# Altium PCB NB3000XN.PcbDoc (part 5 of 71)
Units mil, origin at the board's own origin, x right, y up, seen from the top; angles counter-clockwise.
Board outline 9527.56 x 6929.77 mil, 6 copper layers (Top Layer, GND+SHIELD, MidLayer1, MidLayer2, P2 - 3V3+5V0, Bottom Layer), stack 62.375 mil thick; 832 components, 1027 nets, 4655 pads, 4981 vias.
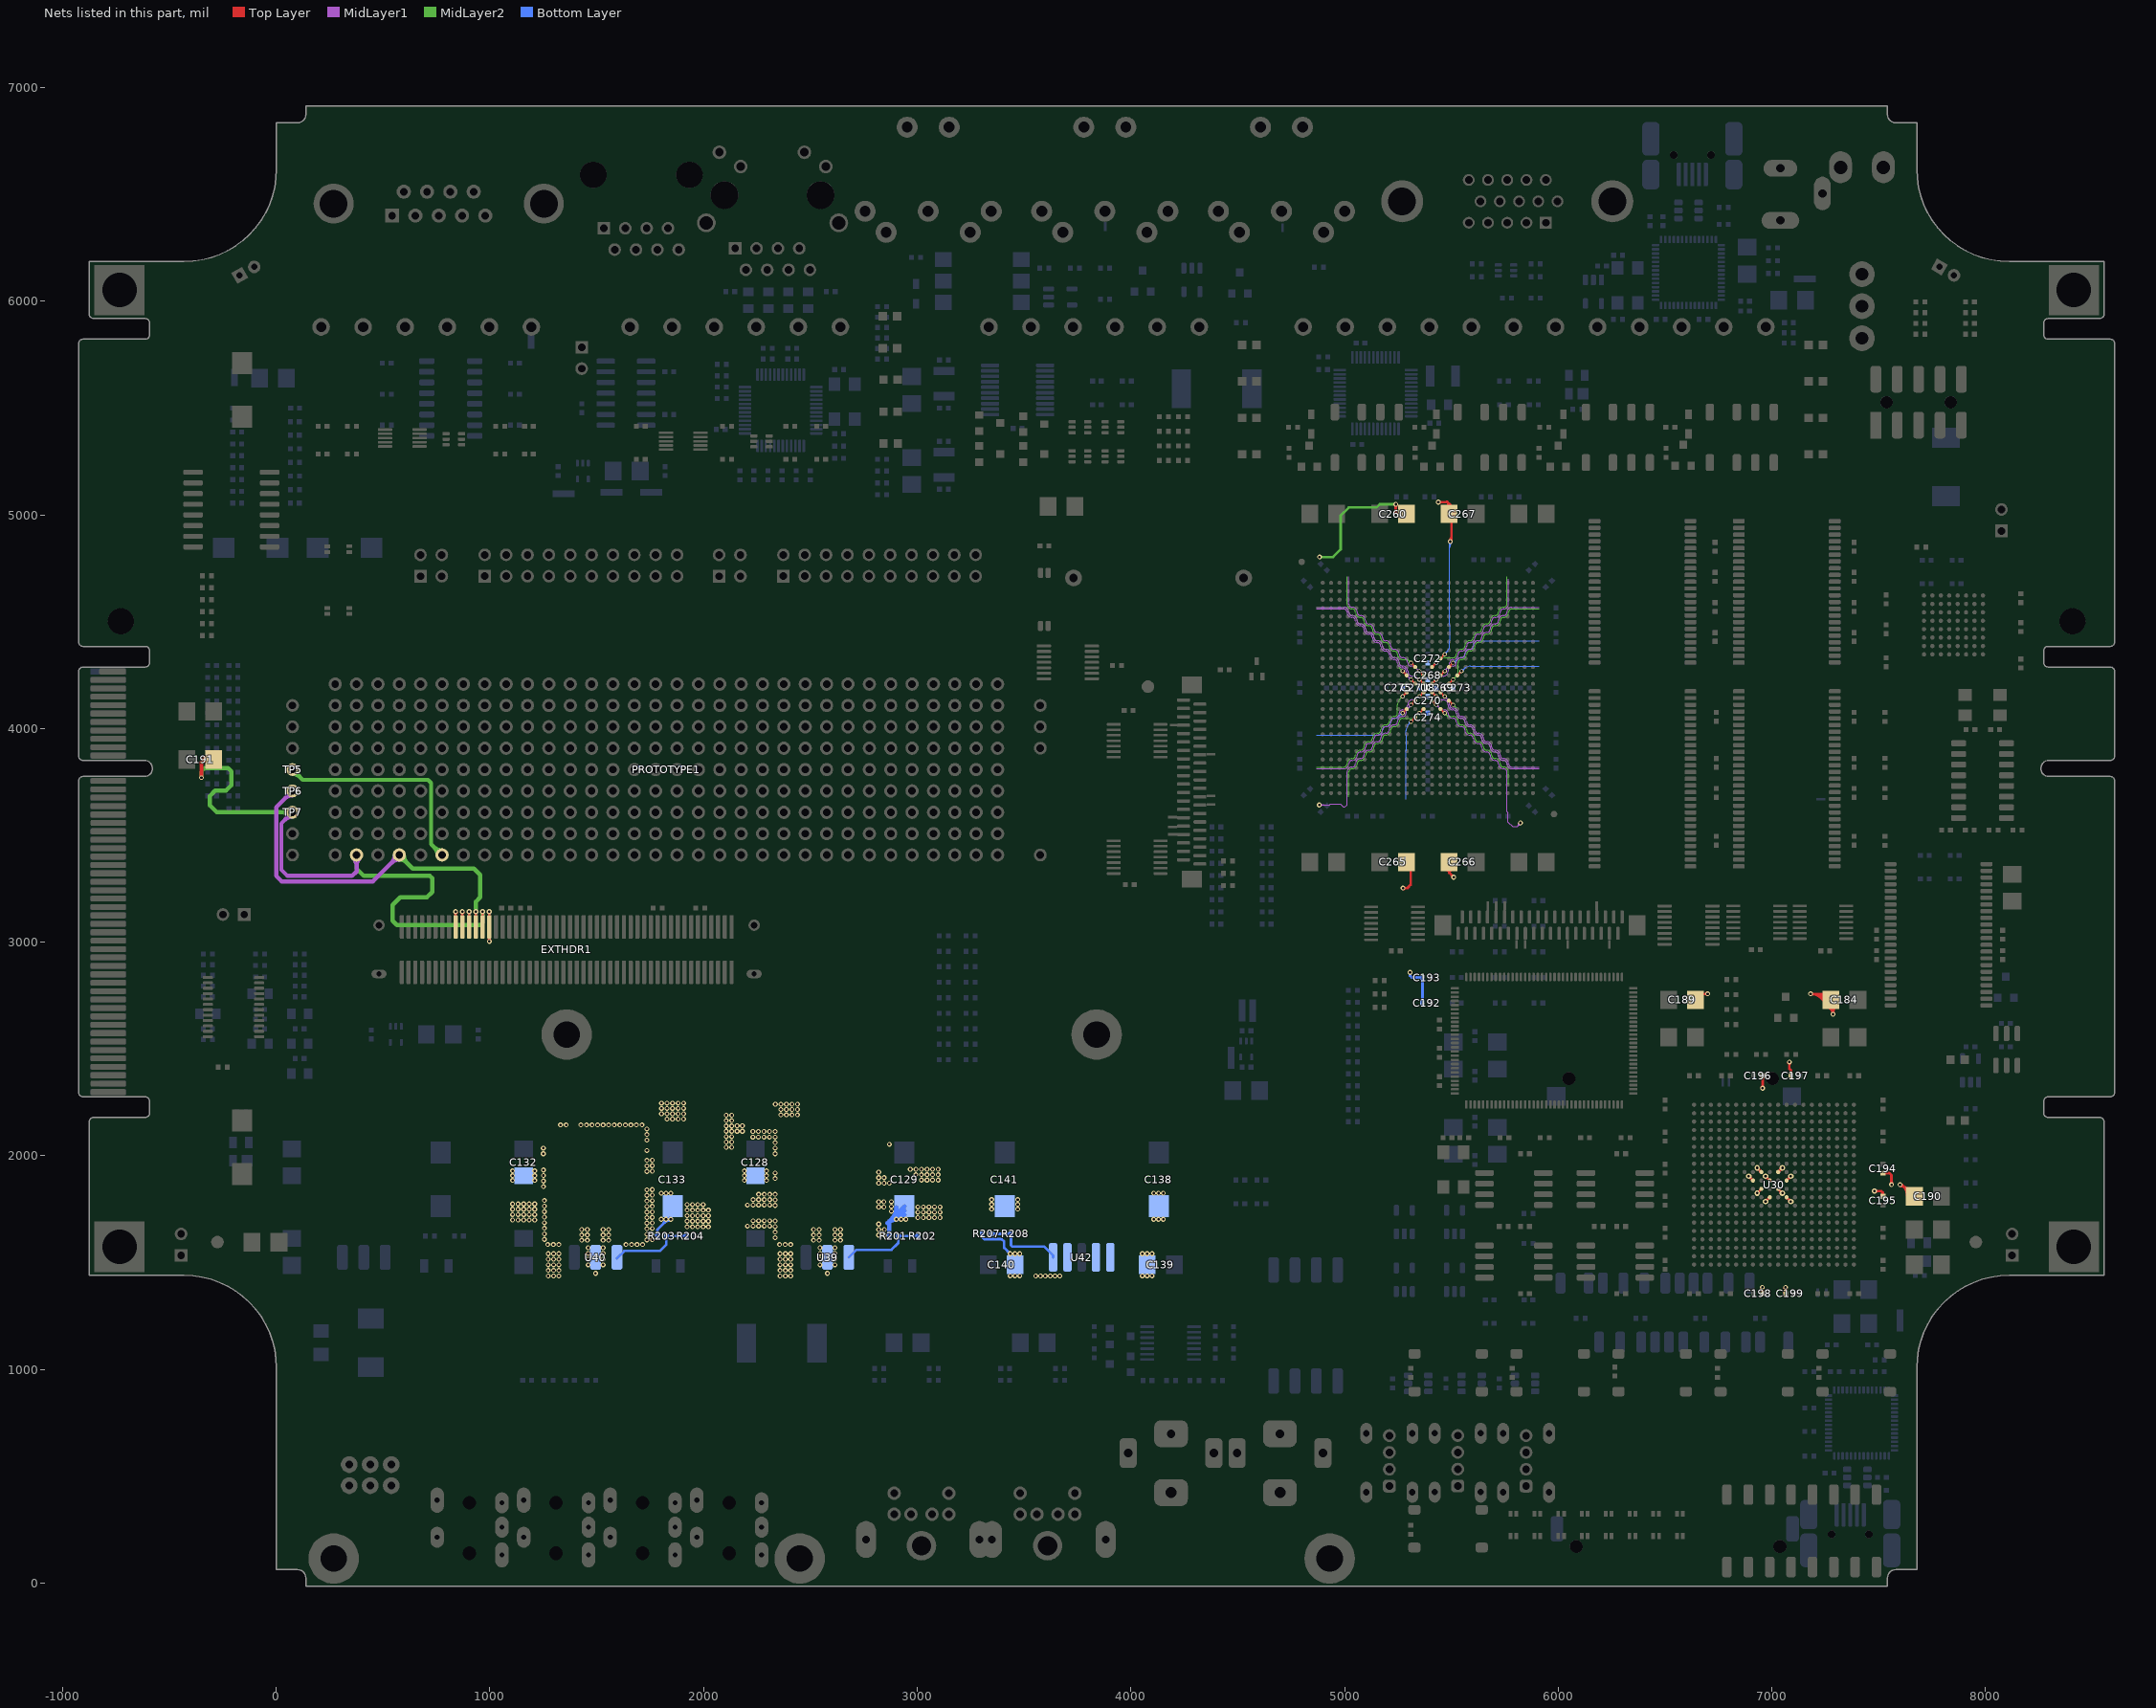
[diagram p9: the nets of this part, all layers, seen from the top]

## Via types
v1: diameter 23, hole 11.81, Top Layer to Bottom Layer, 3672 vias
v2: diameter 26, hole 11.81, Top Layer to Bottom Layer, 461 vias
v3: diameter 19, hole 11.81, Top Layer to Bottom Layer, tented both sides, 396 vias
v4: diameter 23.62, hole 11.81, Top Layer to Bottom Layer, 288 vias
v5: diameter 20, hole 11.81, Top Layer to Bottom Layer, 91 vias
v6: diameter 23, hole 11.81, Top Layer to Bottom Layer, tented both sides, 50 vias
v7: diameter 31, hole 11.81, Top Layer to Bottom Layer, 15 vias
v8: diameter 27.56, hole 11.81, Top Layer to Bottom Layer, tented both sides, 4 vias
v9: diameter 29, hole 11.81, Top Layer to Bottom Layer, 3 vias
v10: diameter 21, hole 11.81, Top Layer to Bottom Layer, 1 vias

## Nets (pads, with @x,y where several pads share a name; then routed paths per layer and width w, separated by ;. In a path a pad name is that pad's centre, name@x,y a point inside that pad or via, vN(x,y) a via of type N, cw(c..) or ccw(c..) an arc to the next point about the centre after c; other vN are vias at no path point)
1V2: C140.1 C141.1 C184.1 C189.1 C190.1 C191.1 C192.1 C193.1 C194.1 C195.1 C196.1 C197.1 C198.1 C199.1 C260.1 C265.1 C266.1 C267.1 C268.1 C269.1 C270.1 C271.1 C272.1 C273.1 C274.1 C275.1 EXTHDR1.73 EXTHDR1.75 PROTOTYPE1.2 R207.2 TP7.1 U8.K15 U8.L12 U8.L14 U8.L16 U8.M11 U8.M13 U8.M15 U8.M17 U8.N12 U8.N13 U8.N14 U8.N16 U8.P11 U8.P13 U8.P14 U8.P15 U8.R12 U8.R14 U8.R16 U8.T11 U8.T13 U8.T15 U8.U12 U30.J10 U30.J12 U30.K9 U30.K11 U30.L10 U30.L12 U30.M9 U30.M11 U30.N10 U42.4 | length 25616.4
  Top Layer w4: v3(5271.89,4071.89) U8.T11@5291.57,4091.57 ; v3(5271.89,4150.63) U8.P11@5291.57,4170.31 ; v3(5271.89,4268.74) U8.M11@5291.57,4249.06 ; U8.T11@5284.07,4091.57 cw(c5265.97,4091.57) 5278.77,4078.77 cw(c5291.57,4065.97) U8.T11@5291.57,4084.07 ; U8.P11@5284.07,4170.32 cw(c5265.97,4170.32) 5278.77,4157.51 cw(c5291.57,4144.71) U8.P11@5291.57,4162.81 ; U8.M11@5284.07,4249.06 ccw(c5265.97,4249.06) 5278.77,4261.86 ccw(c5291.57,4274.66) U8.M11@5291.57,4256.56 ; U8.T11@5284.23,4091.57 cw(c5266.51,4091.57) 5279.04,4079.04 cw(c5291.57,4066.51) U8.T11@5291.57,4084.23 ; U8.P11@5284.23,4170.32 cw(c5266.51,4170.32) 5279.04,4157.78 cw(c5291.57,4145.25) U8.P11@5291.57,4162.97 ; U8.M11@5284.23,4249.06 ccw(c5266.51,4249.06) 5279.04,4261.59 ccw(c5291.57,4274.12) U8.M11@5291.57,4256.4 ; v3(5311.26,4032.52) U8.U12@5330.94,4052.2 ; v3(5311.26,4111.26) U8.R12@5330.94,4130.94 ; v3(5311.26,4229.37) U8.N12@5330.94,4209.69 ; v3(5311.26,4308.11) U8.L12@5330.94,4288.43 ; U8.U12@5323.44,4052.2 cw(c5305.34,4052.2) 5318.14,4039.4 cw(c5330.94,4026.6) U8.U12@5330.94,4044.7 ; U8.R12@5323.44,4130.94 cw(c5305.34,4130.94) 5318.14,4118.14 cw(c5330.94,4105.34) U8.R12@5330.94,4123.44 ; U8.N12@5323.44,4209.69 ccw(c5305.34,4209.68) 5318.14,4222.49 ccw(c5330.94,4235.29) U8.N12@5330.94,4217.19 ; U8.L12@5323.44,4288.43 ccw(c5305.34,4288.43) 5318.14,4301.23 ccw(c5330.94,4314.03) U8.L12@5330.94,4295.93 ; U8.U12@5323.6,4052.2 cw(c5305.88,4052.2) 5318.41,4039.67 cw(c5330.94,4027.14) U8.U12@5330.94,4044.86 ; U8.R12@5323.6,4130.94 cw(c5305.88,4130.94) 5318.41,4118.41 cw(c5330.94,4105.88) U8.R12@5330.94,4123.6 ; U8.N12@5323.6,4209.69 ccw(c5305.88,4209.68) 5318.41,4222.22 ccw(c5330.94,4234.75) U8.N12@5330.94,4217.03 ; U8.L12@5323.6,4288.43 ccw(c5305.88,4288.43) 5318.41,4300.96 ccw(c5330.94,4313.49) U8.L12@5330.94,4295.77 ; v3(5350.63,4071.89) U8.T13@5370.31,4091.57 ; v3(5350.63,4150.63) U8.P13@5370.31,4170.31 ; v3(5350.63,4229.37) U8.N13@5370.31,4209.69 ; v3(5350.63,4268.74) U8.M13@5370.31,4249.06 ; U8.T13@5362.81,4091.57 cw(c5344.71,4091.57) 5357.51,4078.77 cw(c5370.31,4065.97) U8.T13@5370.31,4084.07 ; U8.P13@5362.81,4170.32 cw(c5344.71,4170.32) 5357.51,4157.51 cw(c5370.31,4144.71) U8.P13@5370.31,4162.81 ; U8.N13@5362.81,4209.69 ccw(c5344.71,4209.68) 5357.51,4222.49 ccw(c5370.31,4235.29) U8.N13@5370.31,4217.19 ; U8.M13@5362.81,4249.06 ccw(c5344.71,4249.06) 5357.51,4261.86 ccw(c5370.31,4274.66) U8.M13@5370.31,4256.56 ; U8.T13@5362.97,4091.57 cw(c5345.25,4091.57) 5357.78,4079.04 cw(c5370.31,4066.51) U8.T13@5370.31,4084.23 ; U8.P13@5362.97,4170.32 cw(c5345.25,4170.32) 5357.78,4157.78 cw(c5370.31,4145.25) U8.P13@5370.31,4162.97 ; U8.N13@5362.97,4209.69 ccw(c5345.25,4209.68) 5357.78,4222.22 ccw(c5370.31,4234.75) U8.N13@5370.31,4217.03 ; U8.M13@5362.97,4249.06 ccw(c5345.25,4249.06) 5357.78,4261.59 ccw(c5370.31,4274.12) U8.M13@5370.31,4256.4 ; U8.R14@5409.69,4123.44 cw(c5409.69,4105.34) 5422.49,4118.14 cw(c5435.29,4130.94) U8.R14@5417.19,4130.94 ; U8.R14@5409.69,4123.6 cw(c5409.69,4105.88) 5422.22,4118.41 cw(c5434.75,4130.94) U8.R14@5417.03,4130.94 ; U8.R14@5409.69,4130.94 v3(5429.37,4111.26) ; U8.P14@5409.69,4162.81 cw(c5409.69,4144.71) 5422.49,4157.51 cw(c5435.29,4170.32) U8.P14@5417.19,4170.32 ; U8.P14@5409.69,4162.97 cw(c5409.69,4145.25) 5422.22,4157.78 cw(c5434.75,4170.32) U8.P14@5417.03,4170.32 ; U8.P14@5409.69,4170.31 v3(5429.37,4150.63) ; U8.N14@5409.69,4209.69 v3(5429.37,4229.37) ; U8.N14@5409.69,4217.03 ccw(c5409.69,4234.75) 5422.22,4222.22 ccw(c5434.75,4209.68) U8.N14@5417.03,4209.69 ; U8.N14@5409.69,4217.19 ccw(c5409.69,4235.29) 5422.49,4222.49 ccw(c5435.29,4209.68) U8.N14@5417.19,4209.69 ; U8.L14@5409.69,4288.43 v3(5429.37,4308.11) ; U8.L14@5409.69,4295.77 ccw(c5409.69,4313.49) 5422.22,4300.96 ccw(c5434.75,4288.43) U8.L14@5417.03,4288.43 ; U8.L14@5409.69,4295.93 ccw(c5409.69,4314.03) 5422.49,4301.23 ccw(c5435.29,4288.43) U8.L14@5417.19,4288.43 ; U8.T15@5449.06,4084.07 cw(c5449.06,4065.97) 5461.86,4078.77 cw(c5474.66,4091.57) U8.T15@5456.56,4091.57 ; U8.T15@5449.06,4084.23 cw(c5449.06,4066.51) 5461.59,4079.04 cw(c5474.12,4091.57) U8.T15@5456.4,4091.57 ; U8.T15@5449.06,4091.57 v3(5468.74,4071.89) ; U8.P15@5449.06,4162.81 cw(c5449.06,4144.71) 5461.86,4157.51 cw(c5474.66,4170.32) U8.P15@5456.56,4170.32 ; U8.P15@5449.06,4162.97 cw(c5449.06,4145.25) 5461.59,4157.78 cw(c5474.12,4170.32) U8.P15@5456.4,4170.32 ; U8.P15@5449.06,4170.31 v3(5468.74,4150.63) ; U8.M15@5449.06,4249.06 v3(5468.74,4268.74) ; U8.M15@5449.06,4256.4 ccw(c5449.06,4274.12) 5461.59,4261.59 ccw(c5474.12,4249.06) U8.M15@5456.4,4249.06 ; U8.M15@5449.06,4256.56 ccw(c5449.06,4274.66) 5461.86,4261.86 ccw(c5474.66,4249.06) U8.M15@5456.56,4249.06 ; U8.K15@5449.06,4327.8 v3(5468.74,4347.48) ; U8.K15@5449.06,4335.14 ccw(c5449.06,4352.86) 5461.59,4340.33 ccw(c5474.12,4327.8) U8.K15@5456.4,4327.8 ; U8.K15@5449.06,4335.3 ccw(c5449.06,4353.4) 5461.86,4340.6 ccw(c5474.66,4327.8) U8.K15@5456.56,4327.8 ; U8.R16@5488.43,4123.44 cw(c5488.43,4105.34) 5501.23,4118.14 cw(c5514.03,4130.94) U8.R16@5495.93,4130.94 ; U8.R16@5488.43,4123.6 cw(c5488.43,4105.88) 5500.96,4118.41 cw(c5513.49,4130.94) U8.R16@5495.77,4130.94 ; U8.R16@5488.43,4130.94 v3(5508.11,4111.26) ; U8.N16@5488.43,4209.69 v3(5508.11,4229.37) ; U8.N16@5488.43,4217.03 ccw(c5488.43,4234.75) 5500.96,4222.22 ccw(c5513.49,4209.68) U8.N16@5495.77,4209.69 ; U8.N16@5488.43,4217.19 ccw(c5488.43,4235.29) 5501.23,4222.49 ccw(c5514.03,4209.68) U8.N16@5495.93,4209.69 ; U8.L16@5488.43,4288.43 v3(5508.11,4308.11) ; U8.L16@5488.43,4295.77 ccw(c5488.43,4313.49) 5500.96,4300.96 ccw(c5513.49,4288.43) U8.L16@5495.77,4288.43 ; U8.L16@5488.43,4295.93 ccw(c5488.43,4314.03) 5501.23,4301.23 ccw(c5514.03,4288.43) U8.L16@5495.93,4288.43 ; U8.M17@5527.8,4249.06 v3(5547.48,4268.74) ; U8.M17@5527.8,4256.4 ccw(c5527.8,4274.12) 5540.33,4261.59 ccw(c5552.86,4249.06) U8.M17@5535.14,4249.06 ; U8.M17@5527.8,4256.56 ccw(c5527.8,4274.66) 5540.6,4261.86 ccw(c5553.4,4249.06) U8.M17@5535.3,4249.06 ; C196.1@6956.86,2375 C196.1@6956.86,2376.19 ; v1@5234.86,5050.04 5240,5050.04 v1@5234.9,5050 ; v1@5234.86,5050.04 v1@5234.9,5050 ; 5284.69,4084.69 cw(c5271.89,4097.5) 5271.89,4079.39 ccw(c5271.89,4097.5) 5284.69,4084.69 ; 5284.69,4084.69 ccw(c5297.5,4071.89) 5279.39,4071.89 cw(c5297.5,4071.89) 5284.69,4084.69 ; 5284.69,4163.43 cw(c5271.89,4176.24) 5271.89,4158.13 ccw(c5271.89,4176.24) 5284.69,4163.43 ; 5284.69,4163.43 ccw(c5297.5,4150.63) 5279.39,4150.63 cw(c5297.5,4150.63) 5284.69,4163.43 ; 5284.69,4255.94 cw(c5297.5,4268.74) 5279.39,4268.74 ccw(c5297.5,4268.74) 5284.69,4255.94 ; 5284.69,4255.94 ccw(c5271.89,4243.13) 5271.89,4261.24 cw(c5271.89,4243.13) 5284.69,4255.94 ; 5324.06,4045.32 cw(c5311.26,4058.13) 5311.26,4040.02 ccw(c5311.26,4058.13) 5324.06,4045.32 ; 5324.06,4045.32 ccw(c5336.87,4032.52) 5318.76,4032.52 cw(c5336.87,4032.52) 5324.06,4045.32 ; 5324.06,4124.06 cw(c5311.26,4136.87) 5311.26,4118.76 ccw(c5311.26,4136.87) 5324.06,4124.06 ; 5324.06,4124.06 ccw(c5336.87,4111.26) 5318.76,4111.26 cw(c5336.87,4111.26) 5324.06,4124.06 ; 5324.06,4216.57 cw(c5336.87,4229.37) 5318.76,4229.37 ccw(c5336.87,4229.37) 5324.06,4216.57 ; 5324.06,4216.57 ccw(c5311.26,4203.76) 5311.26,4221.87 cw(c5311.26,4203.76) 5324.06,4216.57 ; 5324.06,4295.31 cw(c5336.87,4308.11) 5318.76,4308.11 ccw(c5336.87,4308.11) 5324.06,4295.31 ; 5324.06,4295.31 ccw(c5311.26,4282.5) 5311.26,4300.61 cw(c5311.26,4282.5) 5324.06,4295.31 ; 5363.43,4084.69 cw(c5350.63,4097.5) 5350.63,4079.39 ccw(c5350.63,4097.5) 5363.43,4084.69 ; 5363.43,4084.69 ccw(c5376.24,4071.89) 5358.13,4071.89 cw(c5376.24,4071.89) 5363.43,4084.69 ; 5363.43,4163.43 cw(c5350.63,4176.24) 5350.63,4158.13 ccw(c5350.63,4176.24) 5363.43,4163.43 ; 5363.43,4163.43 ccw(c5376.24,4150.63) 5358.13,4150.63 cw(c5376.24,4150.63) 5363.43,4163.43 ; 5363.43,4216.57 cw(c5376.24,4229.37) 5358.13,4229.37 ccw(c5376.24,4229.37) 5363.43,4216.57 ; 5363.43,4216.57 ccw(c5350.63,4203.76) 5350.63,4221.87 cw(c5350.63,4203.76) 5363.43,4216.57 ; 5363.43,4255.94 cw(c5376.24,4268.74) 5358.13,4268.74 ccw(c5376.24,4268.74) 5363.43,4255.94 ; 5363.43,4255.94 ccw(c5350.63,4243.13) 5350.63,4261.24 cw(c5350.63,4243.13) 5363.43,4255.94 ; 5416.57,4124.06 cw(c5403.76,4111.26) 5421.87,4111.26 ccw(c5403.76,4111.26) 5416.57,4124.06 ; 5416.57,4124.06 ccw(c5429.37,4136.87) 5429.37,4118.76 cw(c5429.37,4136.87) 5416.57,4124.06 ; 5416.57,4163.43 cw(c5403.76,4150.63) 5421.87,4150.63 ccw(c5403.76,4150.63) 5416.57,4163.43 ; 5416.57,4163.43 ccw(c5429.37,4176.24) 5429.37,4158.13 cw(c5429.37,4176.24) 5416.57,4163.43 ; 5416.57,4216.57 cw(c5429.37,4203.76) 5429.37,4221.87 ccw(c5429.37,4203.76) 5416.57,4216.57 ; 5416.57,4216.57 ccw(c5403.76,4229.37) 5421.87,4229.37 cw(c5403.76,4229.37) 5416.57,4216.57 ; 5416.57,4295.31 cw(c5429.37,4282.5) 5429.37,4300.61 ccw(c5429.37,4282.5) 5416.57,4295.31 ; 5416.57,4295.31 ccw(c5403.76,4308.11) 5421.87,4308.11 cw(c5403.76,4308.11) 5416.57,4295.31 ; 5455.94,4084.69 cw(c5443.13,4071.89) 5461.24,4071.89 ccw(c5443.13,4071.89) 5455.94,4084.69 ; 5455.94,4084.69 ccw(c5468.74,4097.5) 5468.74,4079.39 cw(c5468.74,4097.5) 5455.94,4084.69 ; 5455.94,4163.43 cw(c5443.13,4150.63) 5461.24,4150.63 ccw(c5443.13,4150.63) 5455.94,4163.43 ; 5455.94,4163.43 ccw(c5468.74,4176.24) 5468.74,4158.13 cw(c5468.74,4176.24) 5455.94,4163.43 ; 5455.94,4255.94 cw(c5468.74,4243.13) 5468.74,4261.24 ccw(c5468.74,4243.13) 5455.94,4255.94 ; 5455.94,4255.94 ccw(c5443.13,4268.74) 5461.24,4268.74 cw(c5443.13,4268.74) 5455.94,4255.94 ; 5455.94,4334.68 cw(c5468.74,4321.87) 5468.74,4339.98 ccw(c5468.74,4321.87) 5455.94,4334.68 ; 5455.94,4334.68 ccw(c5443.13,4347.48) 5461.24,4347.48 cw(c5443.13,4347.48) 5455.94,4334.68 ; 5495.31,4124.06 cw(c5482.5,4111.26) 5500.61,4111.26 ccw(c5482.5,4111.26) 5495.31,4124.06 ; 5495.31,4124.06 ccw(c5508.11,4136.87) 5508.11,4118.76 cw(c5508.11,4136.87) 5495.31,4124.06 ; 5495.31,4216.57 cw(c5508.11,4203.76) 5508.11,4221.87 ccw(c5508.11,4203.76) 5495.31,4216.57 ; 5495.31,4216.57 ccw(c5482.5,4229.37) 5500.61,4229.37 cw(c5482.5,4229.37) 5495.31,4216.57 ; 5495.31,4295.31 cw(c5508.11,4282.5) 5508.11,4300.61 ccw(c5508.11,4282.5) 5495.31,4295.31 ; 5495.31,4295.31 ccw(c5482.5,4308.11) 5500.61,4308.11 cw(c5482.5,4308.11) 5495.31,4295.31 ; 5534.68,4255.94 cw(c5547.48,4243.13) 5547.48,4261.24 ccw(c5547.48,4243.13) 5534.68,4255.94 ; 5534.68,4255.94 ccw(c5521.87,4268.74) 5539.98,4268.74 cw(c5521.87,4268.74) 5534.68,4255.94
  Top Layer w8: v2@6891.89,1895.37 cw(c6891.89,1873.64) 6907.25,1889.01 cw(c6922.62,1904.37) v2@6900.89,1904.37 ; v2(6891.89,1904.37) U30.N10@6911.57,1884.68 ; U30.N10@6905.73,1884.68 ccw(c6891.63,1884.68) 6901.6,1894.66 ccw(c6911.57,1904.63) U30.N10@6911.57,1890.53 ; v2(6931.26,1825.63) U30.M11@6950.94,1845.31 ; v2@6931.26,1834.63 ccw(c6931.26,1856.36) 6946.62,1840.99 ccw(c6961.99,1825.63) v2@6940.26,1825.63 ; v2@6931.26,1934.74 cw(c6931.26,1913.01) 6946.62,1928.38 cw(c6961.99,1943.74) v2@6940.26,1943.74 ; v2(6931.26,1943.74) U30.M9@6950.94,1924.06 ; U30.M11@6945.1,1845.31 cw(c6931,1845.31) 6940.97,1835.34 cw(c6950.94,1825.37) U30.M11@6950.94,1839.47 ; U30.M9@6945.1,1924.06 ccw(c6931,1924.06) 6940.97,1934.03 ccw(c6950.94,1944) U30.M9@6950.94,1929.9 ; v2(6970.63,1786.26) U30.L12@6990.31,1805.94 ; v2@6970.63,1795.26 ccw(c6970.63,1816.99) 6985.99,1801.62 ccw(c7001.36,1786.26) v2@6979.63,1786.26 ; v2@6970.63,1895.37 cw(c6970.63,1873.64) 6985.99,1889.01 cw(c7001.36,1904.37) v2@6979.63,1904.37 ; v2(6970.63,1904.37) U30.L10@6990.31,1884.68 ; U30.L12@6984.47,1805.94 cw(c6970.37,1805.94) 6980.34,1795.97 cw(c6990.31,1786) U30.L12@6990.31,1800.1 ; U30.L10@6984.47,1884.68 ccw(c6970.37,1884.68) 6980.34,1894.66 ccw(c6990.31,1904.63) U30.L10@6990.31,1890.53 ; U30.K11@7029.69,1839.47 cw(c7029.69,1825.37) 7039.66,1835.34 cw(c7049.63,1845.31) U30.K11@7035.53,1845.31 ; U30.K11@7029.69,1845.31 v2(7049.37,1825.63) ; U30.K9@7029.69,1924.06 v2(7049.37,1943.74) ; U30.K9@7029.69,1929.9 ccw(c7029.69,1944) 7039.66,1934.03 ccw(c7049.63,1924.06) U30.K9@7035.53,1924.06 ; v2@7040.37,1825.63 ccw(c7018.64,1825.63) 7034.01,1840.99 ccw(c7049.37,1856.36) v2@7049.37,1834.63 ; v2@7040.37,1943.74 cw(c7018.64,1943.74) 7034.01,1928.38 cw(c7049.37,1913.01) v2@7049.37,1934.74 ; U30.J12@7069.06,1800.1 cw(c7069.06,1786) 7079.03,1795.97 cw(c7089,1805.94) U30.J12@7074.9,1805.94 ; U30.J12@7069.06,1805.94 v2(7088.74,1786.26) ; U30.J10@7069.06,1884.68 v2(7088.74,1904.37) ; U30.J10@7069.06,1890.53 ccw(c7069.06,1904.63) 7079.03,1894.66 ccw(c7089,1884.68) U30.J10@7074.9,1884.68 ; v2@7079.74,1786.26 ccw(c7058.01,1786.26) 7073.38,1801.62 ccw(c7088.74,1816.99) v2@7088.74,1795.26 ; v2@7079.74,1904.37 cw(c7058.01,1904.37) 7073.38,1889.01 cw(c7088.74,1873.64) v2@7088.74,1895.37
  Top Layer w12: C191.1@-304.81,3842.2 C191.1@-292.01,3855 ; v1@961.92,3139.15 cw(c952.15,3129.38) 965.97,3129.38 ; EXTHDR1.75@965.97,3071.85 v1@965.97,3142.88 ; 965.97,3130.14 cw(c978.71,3130.14) v1@969.7,3139.15 ; v1@993.42,3139.15 cw(c983.65,3129.38) 997.46,3129.38 ; v1@993.73,3007.7 ccw(c984.72,3016.71) 997.46,3016.71 ; v1@997.46,3003.96 EXTHDR1.73@997.46,3071.85 ; EXTHDR1.73@997.46,3017.46 ccw(c1011.28,3017.46) v1@1001.51,3007.7 ; EXTHDR1.73@997.46,3075 EXTHDR1.73@997.46,3071.85 ; 997.46,3130.14 cw(c1010.21,3130.14) v1@1001.2,3139.15 ; v1@997.46,3142.88 EXTHDR1.73@997.46,3071.85 ; v1@5236.11,5046.11 cw(c5226.72,5036.72) 5240,5036.72 cw(c5253.28,5036.72) v1@5243.89,5046.11 ; v1(5240,5050) 5240,5015 5250,5005 ; C260.1@5257.53,4998.77 ccw(c5250,4997.33) 5250,5005 ; C260.1@5257.53,5011.23 cw(c5250,5012.67) 5250,5005 ; v1(5273.52,3253.37) 5294.52,3253.37 5310,3268.85 5310,3345.31 5290.31,3365 C265.1@5290.31,3375 ; v1@5277.41,3249.49 cw(c5286.8,3240.1) 5286.8,3253.37 cw(c5286.8,3266.65) v1@5277.41,3257.26 ; C260.1@5290.31,5005 5250,5005 ; v1(5438.86,5059.71) 5481.69,5059.71 5489.68,5051.71 ; v1@5442.75,5055.82 cw(c5452.14,5046.43) 5452.14,5059.71 cw(c5452.14,5072.99) v1@5442.75,5063.6 ; 5479.46,5061.94 cw(c5454.23,5036.72) C267.1@5482.31,5014.72 ; C266.1@5479.65,3339.24 cw(c5475.33,3325.55) 5489.69,3325.55 ; C267.1@5481.57,5041.31 ccw(c5478.96,5051.71) 5489.68,5051.71 ; 5489.03,5052.36 cw(c5464.97,5028.3) C267.1@5491.76,5007.32 ; C266.1@5489.68,3375 5489.69,3325.55 ; v1@5491.11,4878.89 ccw(c5466.78,4903.22) 5501.19,4903.22 ; C267.1@5497.8,5041.31 cw(c5500.41,5051.71) 5489.69,5051.71 ; C266.1@5499.72,3339.24 ccw(c5504.04,3325.55) 5489.69,3325.55 ; v1@5501.19,4875 5501.19,4993.49 C267.1@5489.68,5005 5489.68,5051.71 ; v1@5505.69,3304.04 ccw(c5492.41,3304.04) 5501.8,3313.43 ccw(c5511.19,3322.82) v1@5511.19,3309.54 ; v1(5511.19,3304.04) 5489.69,3325.55 ; C189.1@6642.99,2730 6671.37,2758.37 v1(6699.86,2758.37) ; v1@6695.97,2754.49 ccw(c6686.58,2745.1) 6686.58,2758.37 ccw(c6686.58,2771.65) v1@6695.97,2762.26 ; C198.1@6951.56,1359.11 ccw(c6941.64,1369.03) 6955.67,1369.03 ccw(c6969.7,1369.03) C198.1@6959.78,1359.11 ; C196.1@6951.56,2370.89 cw(c6938.77,2358.1) 6956.86,2358.1 ; v1@6951.78,1380.44 cw(c6942.39,1371.05) 6955.67,1371.05 cw(c6968.95,1371.05) v1@6959.56,1380.44 ; v1@6952.97,2320.6 ccw(c6943.58,2329.99) 6956.86,2329.99 ccw(c6970.14,2329.99) v1@6960.75,2320.6 ; C198.1@6955.67,1355 v1(6955.67,1384.33) ; C196.1@6955.67,2375 6956.86,2373.81 v1(6956.86,2316.71) ; C199.1@7060.22,1359.11 ccw(c7050.3,1369.03) 7064.33,1369.03 ccw(c7078.36,1369.03) C199.1@7068.44,1359.11 ; v1@7060.44,1380.44 cw(c7051.05,1371.05) 7064.33,1371.05 cw(c7077.61,1371.05) v1@7068.22,1380.44 ; C199.1@7064.33,1355 v1(7064.33,1384.33) ; v1@7077.97,2435.49 cw(c7068.58,2426.1) 7081.86,2426.1 cw(c7095.14,2426.1) v1@7085.75,2435.49 ; v1(7081.86,2439.37) 7081.86,2408.14 7089.33,2400.67 C197.1@7089.33,2375 ; C197.1@7085.22,2379.11 ccw(c7075.3,2389.03) 7089.33,2389.03 ccw(c7103.36,2389.03) C197.1@7093.44,2379.11 ; v1@7185.08,2754.49 cw(c7194.47,2745.1) 7194.47,2758.37 cw(c7194.47,2771.65) v1@7185.08,2762.26 ; 7201.08,2758.37 cw(c7201.08,2693.92) C184.1@7258.1,2723.97 ; 7220.97,2758.37 cw(c7220.97,2704.4) C184.1@7268.72,2729.57 ; C184.1@7240.86,2758.37 cw(c7240.86,2714.89) C184.1@7279.33,2735.16 ; C184.1@7247.49,2718.38 ccw(c7181.19,2683.44) v1(7181.19,2758.37) 7248.63,2758.37 C184.1@7277.01,2730 7286.52,2720.48 v1(7286.52,2662.71) ; C184.1@7264.29,2695.21 cw(c7250.6,2662) v1@7286.52,2662 ; C184.1@7268.86,2706.31 cw(c7257.99,2679.92) 7286.52,2679.92 ; v1@7282.64,2666.6 ccw(c7273.25,2675.99) 7286.52,2675.99 ccw(c7299.8,2675.99) v1@7290.41,2666.6 ; v1@7286.52,2668.47 cw(c7334.6,2668.47) C184.1@7300.6,2702.47 ; v4(7480,1835) 7513.5,1835 7520,1828.5 C195.1@7520,1810.67 ; v4@7484.11,1830.89 cw(c7494.03,1820.97) 7494.03,1835 cw(c7494.03,1849.03) v4@7484.11,1839.11 ; C195.1@7515.89,1814.78 ccw(c7505.97,1824.7) 7520,1824.7 ccw(c7534.03,1824.7) C195.1@7524.11,1814.78 ; C194.1@7520,1919.33 7550.67,1919.33 7560,1910 v4(7560,1865) ; C194.1@7524.11,1915.22 cw(c7534.03,1905.3) 7534.03,1919.33 cw(c7534.03,1933.36) C194.1@7524.11,1923.44 ; v4@7555.89,1869.11 ccw(c7545.97,1879.03) 7560,1879.03 ccw(c7574.03,1879.03) v4@7564.11,1869.11 ; v1@7600,1859.5 cw(c7600,1825.98) 7623.7,1849.68 ; v1(7600,1865) 7608.39,1865 7663.39,1810 C190.1@7667.01,1810 C190.1@7665.2,1808.19 ; 7612.17,1861.22 ccw(c7649.88,1898.93) C190.1@7660.41,1846.65 ; 7615.39,1858 cw(c7571.32,1813.94) C190.1@7633.64,1813.94 ; C190.1@7627.99,1845.39 ccw(c7655.19,1872.59) C190.1@7662.79,1834.89
  Top Layer w20: v10(-350,3770) -350,3845 -340,3855 ; -340.86,3854.14 cw(c-309.92,3823.19) C191.1@-286.26,3860.01 ; C191.1@-318.16,3841.64 ccw(c-340,3830.48) -340,3855 ; C191.1@-318.16,3868.36 cw(c-340,3879.52) -340,3855 ; C191.1@-292.01,3855 -340,3855
  MidLayer1 w4: 4870,3811.9 4879.78,3811.9 4938.04,3811.9 4996.3,3811.9 ccw(c4996.3,3835.67) 5020.07,3835.67 cw(c5035.67,3835.67) 5035.67,3851.27 ccw(c5035.67,3875.04) 5059.44,3875.04 cw(c5075.04,3875.04) 5075.04,3890.64 ccw(c5075.04,3914.41) 5098.81,3914.41 cw(c5114.41,3914.41) 5114.41,3930.01 ccw(c5114.41,3953.78) 5138.18,3953.78 cw(c5153.78,3953.78) 5153.78,3969.38 ccw(c5153.78,3993.15) 5177.55,3993.15 cw(c5193.15,3993.15) 5193.15,4008.75 ccw(c5193.15,4032.52) 5216.92,4032.52 cw(c5232.52,4032.52) 5232.52,4048.12 ccw(c5232.52,4071.89) 5256.29,4071.89 cw(c5271.89,4071.89) 5271.89,4087.49 ccw(c5271.89,4111.26) 5295.66,4111.26 cw(c5319.43,4111.26) 5319.43,4135.03 ; 4870,4559.93 4879.78,4559.93 4938.04,4559.93 4996.3,4559.93 cw(c4996.3,4544.33) 5011.9,4544.33 ccw(c5035.67,4544.33) 5035.67,4520.56 cw(c5035.67,4504.96) 5051.27,4504.96 ccw(c5075.04,4504.96) 5075.04,4481.19 cw(c5075.04,4465.59) 5090.64,4465.59 ccw(c5114.41,4465.59) 5114.41,4441.82 cw(c5114.41,4426.22) 5130.01,4426.22 ccw(c5153.78,4426.22) 5153.78,4402.45 cw(c5153.78,4386.85) 5169.38,4386.85 ccw(c5193.15,4386.85) 5193.15,4363.08 cw(c5193.15,4347.48) 5208.75,4347.48 ccw(c5232.52,4347.48) 5232.52,4323.71 cw(c5232.52,4308.11) 5248.12,4308.11 ccw(c5271.89,4308.11) 5271.89,4284.34 cw(c5271.89,4268.74) 5287.49,4268.74 ; 4870,4568.1 4879.78,4568.1 4938.04,4568.1 4996.3,4568.1 cw(c4996.3,4544.33) 5020.07,4544.33 ccw(c5035.67,4544.33) 5035.67,4528.73 cw(c5035.67,4504.96) 5059.44,4504.96 ccw(c5075.04,4504.96) 5075.04,4489.36 cw(c5075.04,4465.59) 5098.81,4465.59 ccw(c5114.41,4465.59) 5114.41,4449.99 cw(c5114.41,4426.22) 5138.18,4426.22 ccw(c5153.78,4426.22) 5153.78,4410.62 cw(c5153.78,4386.85) 5177.55,4386.85 ccw(c5193.15,4386.85) 5193.15,4371.25 cw(c5193.15,4347.48) 5216.92,4347.48 ccw(c5232.52,4347.48) 5232.52,4331.88 cw(c5232.52,4308.11) 5256.29,4308.11 ccw(c5271.89,4308.11) 5271.89,4292.51 cw(c5271.89,4268.74) 5295.66,4268.74 ccw(c5319.43,4268.74) 5319.43,4244.97 ; v1(4881.86,3642.37) 4930,3642.37 4933.5,3645.87 4980.44,3645.87 4993.31,3633 5001.69,3633 5011.9,3643.21 5011.9,3660 5011.9,3670 5011.9,3679.78 5011.9,3738.04 5011.9,3796.3 cw(c5035.67,3796.3) 5035.67,3820.07 ccw(c5035.67,3835.67) 5051.27,3835.67 cw(c5075.04,3835.67) 5075.04,3859.44 ccw(c5075.04,3875.04) 5090.64,3875.04 cw(c5114.41,3875.04) 5114.41,3898.81 ccw(c5114.41,3914.41) 5130.01,3914.41 cw(c5153.78,3914.41) 5153.78,3938.18 ccw(c5153.78,3953.78) 5169.38,3953.78 cw(c5193.15,3953.78) 5193.15,3977.55 ccw(c5193.15,3993.15) 5208.75,3993.15 cw(c5232.52,3993.15) 5232.52,4016.92 ccw(c5232.52,4032.52) 5248.12,4032.52 cw(c5271.89,4032.52) 5271.89,4056.29 ccw(c5271.89,4071.89) 5287.49,4071.89 cw(c5311.26,4071.89) 5294.45,4088.7 5300.87,4096.43 ; v1@4881.86,4800.04 v1@4883,4800.04 ; v1(4883,4803) v1@4885.96,4800.04 ; v1@4885.75,3638.49 cw(c4895.14,3629.1) 4895.14,3642.37 cw(c4895.14,3655.65) v1@4885.75,3646.26 ; v1@4888.57,3635.66 cw(c4904.79,3619.44) 4904.79,3642.37 cw(c4904.79,3665.31) v1@4888.57,3649.09 ; 5020.07,4710 5020.07,4700.22 5020.07,4641.96 5020.07,4583.7 ccw(c5035.67,4583.7) 5035.67,4568.1 cw(c5035.67,4544.33) 5059.44,4544.33 ccw(c5075.04,4544.33) 5075.04,4528.73 cw(c5075.04,4504.96) 5098.81,4504.96 ccw(c5114.41,4504.96) 5114.41,4489.36 cw(c5114.41,4465.59) 5138.18,4465.59 ccw(c5153.78,4465.59) 5153.78,4449.99 cw(c5153.78,4426.22) 5177.55,4426.22 ccw(c5193.15,4426.22) 5193.15,4410.62 cw(c5193.15,4386.85) 5216.92,4386.85 ccw(c5232.52,4386.85) 5232.52,4371.25 cw(c5232.52,4347.48) 5256.29,4347.48 ccw(c5271.89,4347.48) 5271.89,4331.88 cw(c5271.89,4308.11) 5295.66,4308.11 ccw(c5311.26,4308.11) 5311.26,4292.51 ; 5287.4,4269.25 ccw(c5326.07,4269.25) 5298.73,4241.9 ; v3@5303.87,4109.96 cw(c5286.04,4106.81) 5300.87,4096.43 ; v3@5303.92,4229.37 ccw(c5286.19,4229.37) 5298.73,4241.9 ; 5310.75,4292.6 cw(c5310.75,4253.93) 5338.1,4281.27 ; v3@5311.26,4236.71 cw(c5311.26,4254.44) 5298.73,4241.9 ; v3@5312.56,4103.87 ccw(c5315.71,4086.04) 5300.87,4096.43 ; 5319.43,4135.08 ccw(c5321.04,4158.8) 5335.83,4140.2 ; 5319.43,4244.92 cw(c5321.04,4221.2) 5335.83,4239.8 ; v3@5343.24,4151.93 cw(c5325.41,4155.08) 5335.8,4140.24 cw(c5346.18,4125.41) v3@5349.33,4143.24 ; v3@5343.24,4228.07 ccw(c5325.41,4224.92) 5335.8,4239.76 ccw(c5346.18,4254.59) v3@5349.33,4236.76 ; v3@5343.29,4268.74 ccw(c5325.56,4268.74) 5338.1,4281.27 ; v3@5350.63,4276.08 cw(c5350.63,4293.81) 5338.1,4281.27 ; v3@5429.37,4103.92 cw(c5429.37,4086.19) 5441.9,4098.73 ; v3@5430.67,4143.24 cw(c5433.82,4125.41) 5444.2,4140.24 cw(c5454.59,4155.08) v3@5436.76,4151.93 ; v3@5430.67,4236.76 ccw(c5433.82,4254.59) 5444.2,4239.76 ccw(c5454.59,4224.92) v3@5436.76,4228.07 ; v3@5436.71,4111.26 ccw(c5454.44,4111.26) 5441.9,4098.73 ; 5444.17,4140.2 ccw(c5458.96,4158.8) 5460.57,4135.08 ; 5444.17,4239.8 cw(c5458.96,4221.2) 5460.57,4244.92 ; 5460.57,4135.03 cw(c5460.57,4111.26) 5484.34,4111.26 ccw(c5508.11,4111.26) 5508.11,4087.49 cw(c5508.11,4071.89) 5523.71,4071.89 ccw(c5547.48,4071.89) 5547.48,4048.12 cw(c5547.48,4032.52) 5563.08,4032.52 ccw(c5586.85,4032.52) 5586.85,4008.75 cw(c5586.85,3993.15) 5602.45,3993.15 ccw(c5626.22,3993.15) 5626.22,3969.38 cw(c5626.22,3953.78) 5641.82,3953.78 ccw(c5665.59,3953.78) 5665.59,3930.01 cw(c5665.59,3914.41) 5681.19,3914.41 ccw(c5704.96,3914.41) 5704.96,3890.64 cw(c5704.96,3875.04) 5720.56,3875.04 ccw(c5744.33,3875.04) 5744.33,3851.27 cw(c5744.33,3835.67) 5759.93,3835.67 ccw(c5783.7,3835.67) 5783.7,3811.9 5841.96,3811.9 5900.22,3811.9 5910,3811.9 ; 5460.57,4244.97 ccw(c5460.57,4268.74) 5484.34,4268.74 cw(c5508.11,4268.74) 5508.11,4292.51 ccw(c5508.11,4308.11) 5523.71,4308.11 cw(c5547.48,4308.11) 5547.48,4331.88 ccw(c5547.48,4347.48) 5563.08,4347.48 cw(c5586.85,4347.48) 5586.85,4371.25 ccw(c5586.85,4386.85) 5602.45,4386.85 cw(c5626.22,4386.85) 5626.22,4410.62 ccw(c5626.22,4426.22) 5641.82,4426.22 cw(c5665.59,4426.22) 5665.59,4449.99 ccw(c5665.59,4465.59) 5681.19,4465.59 cw(c5704.96,4465.59) 5704.96,4489.36 ccw(c5704.96,4504.96) 5720.56,4504.96 cw(c5744.33,4504.96) 5744.33,4528.73 ccw(c5744.33,4544.33) 5759.93,4544.33 cw(c5783.7,4544.33) 5783.7,4568.1 5841.96,4568.1 5900.22,4568.1 5910,4568.1 ; v3@5467.44,4276.13 ccw(c5464.29,4293.96) 5479.13,4283.57 ; 5468.74,4087.49 cw(c5468.74,4071.89) 5484.34,4071.89 ccw(c5508.11,4071.89) 5508.11,4048.12 cw(c5508.11,4032.52) 5523.71,4032.52 ccw(c5547.48,4032.52) 5547.48,4008.75 cw(c5547.48,3993.15) 5563.08,3993.15 ccw(c5586.85,3993.15) 5586.85,3969.38 cw(c5586.85,3953.78) 5602.45,3953.78 ccw(c5626.22,3953.78) 5626.22,3930.01 cw(c5626.22,3914.41) 5641.82,3914.41 ccw(c5665.59,3914.41) 5665.59,3890.64 cw(c5665.59,3875.04) 5681.19,3875.04 ccw(c5704.96,3875.04) 5704.96,3851.27 cw(c5704.96,3835.67) 5720.56,3835.67 ccw(c5744.33,3835.67) 5744.33,3811.9 cw(c5744.33,3796.3) 5759.93,3796.3 5759.93,3738.04 5759.93,3679.78 5759.93,3670 5759.93,3660 5759.93,3655.26 5759.93,3610.07 5765,3605 5765,3562.82 5786.45,3541.37 5808.63,3541.37 5823.52,3556.27 v1(5823.52,3558.37) ; v3@5468.74,4143.29 cw(c5468.74,4125.56) 5481.27,4138.1 ; 5469.25,4087.4 cw(c5469.25,4126.07) 5441.9,4098.73 ; v3@5476.08,4150.63 ccw(c5493.81,4150.63) 5481.27,4138.1 ; v3@5476.13,4270.04 cw(c5493.96,4273.19) 5479.13,4283.57 ; 5492.51,4111.26 ccw(c5508.11,4111.26) 5508.11,4095.66 cw(c5508.11,4071.89) 5531.88,4071.89 ccw(c5547.48,4071.89) 5547.48,4056.29 cw(c5547.48,4032.52) 5571.25,4032.52 ccw(c5586.85,4032.52) 5586.85,4016.92 cw(c5586.85,3993.15) 5610.62,3993.15 ccw(c5626.22,3993.15) 5626.22,3977.55 cw(c5626.22,3953.78) 5649.99,3953.78 ccw(c5665.59,3953.78) 5665.59,3938.18 cw(c5665.59,3914.41) 5689.36,3914.41 ccw(c5704.96,3914.41) 5704.96,3898.81 cw(c5704.96,3875.04) 5728.73,3875.04 ccw(c5744.33,3875.04) 5744.33,3859.44 cw(c5744.33,3835.67) 5768.1,3835.67 ccw(c5783.7,3835.67) 5783.7,3820.07 5841.96,3820.07 5900.22,3820.07 5910,3820.07 ; 5492.6,4110.75 ccw(c5453.93,4110.75) 5481.27,4138.1 ; 5768.1,4700.22 5768.1,4641.96 5768.1,4583.7 cw(c5744.33,4583.7) 5744.33,4559.93 ccw(c5744.33,4544.33) 5728.73,4544.33 cw(c5704.96,4544.33) 5704.96,4520.56 ccw(c5704.96,4504.96) 5689.36,4504.96 cw(c5665.59,4504.96) 5665.59,4481.19 ccw(c5665.59,4465.59) 5649.99,4465.59 cw(c5626.22,4465.59) 5626.22,4441.82 ccw(c5626.22,4426.22) 5610.62,4426.22 cw(c5586.85,4426.22) 5586.85,4402.45 ccw(c5586.85,4386.85) 5571.25,4386.85 cw(c5547.48,4386.85) 5547.48,4363.08 ccw(c5547.48,4347.48) 5531.88,4347.48 cw(c5508.11,4347.48) 5508.11,4323.71 ccw(c5508.11,4308.11) 5492.51,4308.11 cw(c5468.74,4308.11) 5485.55,4291.3 5479.13,4283.57 ; 5809.68,3542.43 ccw(c5798.22,3553.88) v1@5814.17,3556.71 ; 5810.89,3543.64 cw(c5823.52,3531.01) v1@5823.52,3548.87 ; 5815.1,3547.85 ccw(c5807.44,3555.52) v1@5818.11,3557.41
  MidLayer1 w20: TP7.1@56.12,3608.23 cw(c7.84,3608.23) 41.98,3574.09 cw(c76.12,3539.95) TP7.1@76.12,3588.23 ; TP7.1@76.12,3608.23 24,3556.11 24,3339 53,3310 355,3310 376.12,3331.12 PROTOTYPE1.2@376.12,3408.23 ; PROTOTYPE1.2@361.27,3393.39 cw(c325.42,3357.54) 376.12,3357.54 cw(c426.82,3357.54) PROTOTYPE1.2@390.97,3393.39
  MidLayer2 w4: 4870,3820.07 4879.78,3820.07 4938.04,3820.07 4996.3,3820.07 ccw(c4996.3,3835.67) 5011.9,3835.67 cw(c5035.67,3835.67) 5035.67,3859.44 ccw(c5035.67,3875.04) 5051.27,3875.04 cw(c5075.04,3875.04) 5075.04,3898.81 ccw(c5075.04,3914.41) 5090.64,3914.41 cw(c5114.41,3914.41) 5114.41,3938.18 ccw(c5114.41,3953.78) 5130.01,3953.78 cw(c5153.78,3953.78) 5153.78,3977.55 ccw(c5153.78,3993.15) 5169.38,3993.15 cw(c5193.15,3993.15) 5193.15,4016.92 ccw(c5193.15,4032.52) 5208.75,4032.52 cw(c5232.52,4032.52) 5232.52,4056.29 ccw(c5232.52,4071.89) 5248.12,4071.89 ; 4870,4568.1 4879.78,4568.1 4938.04,4568.1 4996.3,4568.1 cw(c4996.3,4544.33) 5020.07,4544.33 ccw(c5035.67,4544.33) 5035.67,4528.73 cw(c5035.67,4504.96) 5059.44,4504.96 ccw(c5075.04,4504.96) 5075.04,4489.36 cw(c5075.04,4465.59) 5098.81,4465.59 ccw(c5114.41,4465.59) 5114.41,4449.99 cw(c5114.41,4426.22) 5138.18,4426.22 ccw(c5153.78,4426.22) 5153.78,4410.62 cw(c5153.78,4386.85) 5177.55,4386.85 ccw(c5193.15,4386.85) 5193.15,4371.25 cw(c5193.15,4347.48) 5216.92,4347.48 ccw(c5232.52,4347.48) 5232.52,4331.88 cw(c5232.52,4308.11) 5256.29,4308.11 5256.29,4288.55 ; v1@4881.86,4800.04 4883,4801.18 v1(4883,4803) ; 5011.9,4710 5011.9,4700.22 5011.9,4641.96 5011.9,4583.7 ccw(c5035.67,4583.7) 5035.67,4559.93 cw(c5035.67,4544.33) 5051.27,4544.33 ccw(c5075.04,4544.33) 5075.04,4520.56 cw(c5075.04,4504.96) 5090.64,4504.96 ccw(c5114.41,4504.96) 5114.41,4481.19 cw(c5114.41,4465.59) 5130.01,4465.59 ccw(c5153.78,4465.59) 5153.78,4441.82 cw(c5153.78,4426.22) 5169.38,4426.22 ccw(c5193.15,4426.22) 5193.15,4402.45 cw(c5193.15,4386.85) 5208.75,4386.85 ccw(c5232.52,4386.85) 5232.52,4363.08 cw(c5232.52,4347.48) 5248.12,4347.48 ; 5020.07,3679.78 5020.07,3738.04 5020.07,3796.3 cw(c5035.67,3796.3) 5035.67,3811.9 ccw(c5035.67,3835.67) 5059.44,3835.67 cw(c5075.04,3835.67) 5075.04,3851.27 ccw(c5075.04,3875.04) 5098.81,3875.04 cw(c5114.41,3875.04) 5114.41,3890.64 ccw(c5114.41,3914.41) 5138.18,3914.41 cw(c5153.78,3914.41) 5153.78,3930.01 ccw(c5153.78,3953.78) 5177.55,3953.78 cw(c5193.15,3953.78) 5193.15,3969.38 ccw(c5193.15,3993.15) 5216.92,3993.15 cw(c5232.52,3993.15) 5232.52,4008.75 ccw(c5232.52,4032.52) 5256.29,4032.52 ; 5248.03,4071.98 5248.03,4110.75 cw(c5286.7,4110.75) 5259.36,4138.1 ; 5255.08,4330.67 cw(c5271.89,4347.48) 5248.12,4347.48 ; 5256.38,4288.45 ccw(c5266.53,4288.45) 5259.36,4281.27 ; v3@5264.55,4150.63 cw(c5246.82,4150.63) 5259.36,4138.1 ; v3@5264.55,4268.74 ccw(c5246.82,4268.74) 5259.36,4281.27 ; v3@5271.89,4143.29 ccw(c5271.89,4125.56) 5259.36,4138.1 ; v3@5271.89,4276.08 cw(c5271.89,4293.81) 5259.36,4281.27 ; 5271.98,4048.03 5310.75,4048.03 ccw(c5310.75,4086.7) 5338.1,4059.36 ; 5291.45,4323.71 5271.89,4323.71 cw(c5271.89,4347.48) 5248.12,4347.48 ; 5291.55,4323.62 cw(c5291.55,4313.47) 5298.73,4320.64 ; v3@5343.29,4071.89 cw(c5325.56,4071.89) 5338.1,4059.36 ; v3@5350.63,4064.55 ccw(c5350.63,4046.82) 5338.1,4059.36 ; v3@5429.37,4315.45 ccw(c5429.37,4333.18) 5441.9,4320.64 ; v3@5436.71,4308.11 cw(c5454.44,4308.11) 5441.9,4320.64 ; 5488.45,4056.38 cw(c5488.45,4066.53) 5481.27,4059.36 ; 5488.55,4056.29 5508.11,4056.29 cw(c5508.11,4032.52) 5531.88,4032.52 ccw(c5547.48,4032.52) 5547.48,4016.92 cw(c5547.48,3993.15) 5571.25,3993.15 ccw(c5586.85,3993.15) 5586.85,3977.55 cw(c5586.85,3953.78) 5610.62,3953.78 ccw(c5626.22,3953.78) 5626.22,3938.18 cw(c5626.22,3914.41) 5649.99,3914.41 ccw(c5665.59,3914.41) 5665.59,3898.81 cw(c5665.59,3875.04) 5689.36,3875.04 ccw(c5704.96,3875.04) 5704.96,3859.44 cw(c5704.96,3835.67) 5728.73,3835.67 ccw(c5744.33,3835.67) 5744.33,3820.07 cw(c5744.33,3796.3) 5768.1,3796.3 5768.1,3738.04 ; 5508.02,4331.97 5469.25,4331.97 ccw(c5469.25,4293.3) 5441.9,4320.64 ; v3@5508.11,4103.92 cw(c5508.11,4086.19) 5520.64,4098.73 ; v3@5508.11,4236.71 ccw(c5508.11,4254.44) 5520.64,4241.9 ; v3@5515.45,4111.26 ccw(c5533.18,4111.26) 5520.64,4098.73 ; v3@5515.45,4229.37 cw(c5533.18,4229.37) 5520.64,4241.9 ; 5523.62,4091.55 ccw(c5513.47,4091.55) 5520.64,4098.73 ; 5523.71,4091.45 5523.71,4071.89 ccw(c5547.48,4071.89) 5547.48,4048.12 cw(c5547.48,4032.52) 5563.08,4032.52 ccw(c5586.85,4032.52) 5586.85,4008.75 cw(c5586.85,3993.15) 5602.45,3993.15 ccw(c5626.22,3993.15) 5626.22,3969.38 cw(c5626.22,3953.78) 5641.82,3953.78 ccw(c5665.59,3953.78) 5665.59,3930.01 cw(c5665.59,3914.41) 5681.19,3914.41 ccw(c5704.96,3914.41) 5704.96,3890.64 cw(c5704.96,3875.04) 5720.56,3875.04 ccw(c5744.33,3875.04) 5744.33,3851.27 cw(c5744.33,3835.67) 5759.93,3835.67 ccw(c5783.7,3835.67) 5783.7,3811.9 5841.96,3811.9 ; 5531.88,4308.11 cw(c5547.48,4308.11) 5547.48,4323.71 ccw(c5547.48,4347.48) 5571.25,4347.48 cw(c5586.85,4347.48) 5586.85,4363.08 ccw(c5586.85,4386.85) 5610.62,4386.85 cw(c5626.22,4386.85) 5626.22,4402.45 ccw(c5626.22,4426.22) 5649.99,4426.22 cw(c5665.59,4426.22) 5665.59,4441.82 ccw(c5665.59,4465.59) 5689.36,4465.59 cw(c5704.96,4465.59) 5704.96,4481.19 ccw(c5704.96,4504.96) 5728.73,4504.96 cw(c5744.33,4504.96) 5744.33,4520.56 ccw(c5744.33,4544.33) 5768.1,4544.33 cw(c5783.7,4544.33) 5783.7,4559.93 5841.96,4559.93 5900.22,4559.93 5910,4559.93 ; 5531.97,4308.02 5531.97,4269.25 cw(c5493.3,4269.25) 5520.64,4241.9 ; 5759.93,4710 5759.93,4700.22 5759.93,4641.96 5759.93,4583.7 cw(c5744.33,4583.7) 5744.33,4568.1 ccw(c5744.33,4544.33) 5720.56,4544.33 cw(c5704.96,4544.33) 5704.96,4528.73 ccw(c5704.96,4504.96) 5681.19,4504.96 cw(c5665.59,4504.96) 5665.59,4489.36 ccw(c5665.59,4465.59) 5641.82,4465.59 cw(c5626.22,4465.59) 5626.22,4449.99 ccw(c5626.22,4426.22) 5602.45,4426.22 cw(c5586.85,4426.22) 5586.85,4410.62 ccw(c5586.85,4386.85) 5563.08,4386.85 cw(c5547.48,4386.85) 5547.48,4371.25 ccw(c5547.48,4347.48) 5523.71,4347.48 ; 5256.29,4032.52 cw(c5271.89,4032.52) 5271.89,4048.12 ccw(c5271.89,4032.52) 5256.29,4032.52 ; 5298.73,4320.64 cw(c5286.19,4308.11) 5303.92,4308.11 ccw(c5286.19,4308.11) 5298.73,4320.64 ; 5298.73,4320.64 ccw(c5311.26,4333.18) 5311.26,4315.45 cw(c5311.26,4333.18) 5298.73,4320.64 ; v3@5476.08,4071.89 ccw(c5493.81,4071.89) 5481.27,4059.36 ; v3@5476.08,4071.89 ccw(c5493.81,4071.89) 5481.27,4059.36 ; v3@5476.08,4071.89 ccw(c5493.81,4071.89) 5481.27,4059.36 ; 5481.27,4059.36 ccw(c5468.74,4046.82) 5468.74,4064.55 cw(c5468.74,4046.82) 5481.27,4059.36 ; 5523.71,4347.48 cw(c5508.11,4347.48) 5508.11,4331.88 ccw(c5508.11,4347.48) 5523.71,4347.48
  MidLayer2 w12: v1@4883,4801.18 4883.91,4802.09 4884.82,4803 4946.41,4803 4982.36,4838.95 4982.36,4997.36 5020,5035 5150,5035 5165.04,5050.04 5239.96,5050.04 v1(5240,5050) ; v1@4886.89,4799.11 cw(c4896.28,4789.72) 4896.28,4803 cw(c4896.28,4816.28) v1@4886.89,4806.89 ; 5226.62,5050.04 cw(c5226.62,5036.62) v1@5236.11,5046.11 ; 5226.82,5050.04 ccw(c5226.82,5063.18) v1@5236.11,5053.89
  MidLayer2 w20: v10(-350,3770) -350,3800 -335,3815 -225,3815 -210,3800 -210,3735 -235.5,3709.5 -285.5,3709.5 -310,3685 -310,3640 -278.23,3608.23 TP7.1@76.12,3608.23 ; TP7.1@61.98,3594.09 ccw(c27.84,3559.95) 27.84,3608.23 ccw(c27.84,3656.52) TP7.1@61.98,3622.38 ; PROTOTYPE1.2@361.27,3393.39 cw(c325.42,3357.54) 376.12,3357.54 cw(c426.82,3357.54) PROTOTYPE1.2@390.97,3393.39 ; PROTOTYPE1.2@376.12,3408.23 376.12,3343.88 410,3310 720,3310 730,3300 730,3235 705,3210 580,3210 545,3175 545,3100 565,3080 955,3080 965.81,3090.81 v1(965.81,3143.04)
  Bottom Layer w4: 4870,3969.29 5076.1,3969.29 ; 4938.04,3969.38 5153.78,3969.38 ccw(c5153.78,3993.15) 5177.55,3993.15 cw(c5193.15,3993.15) 5193.15,4008.75 ccw(c5193.15,4032.52) 5216.92,4032.52 cw(c5232.52,4032.52) 5232.52,4048.12 ccw(c5232.52,4071.89) 5249.33,4055.08 5257.06,4061.5 ; v1@5237.45,5047.45 v1@5234.9,5050 ; v1(5240,5050) v1@5234.9,5050 ; v3@5264.5,4073.19 cw(c5246.67,4076.34) 5257.06,4061.5 ; v3@5270.59,4064.5 ccw(c5267.44,4046.67) 5257.06,4061.5 ; v1(5273.52,3253.37) v1@5277.52,3257.37 ; 5287.4,3670 5287.4,3876.1 ; 5287.4,3677.4 5287.4,3895.52 5287.4,3969.64 5287.4,3989.14 cw(c5329.13,3989.14) 5299.62,4018.65 ; v3@5303.79,4031.87 cw(c5285.75,4030.29) 5299.62,4018.65 ; v3@5311.91,4025.05 ccw(c5313.49,4007.01) 5299.62,4018.65 ; v3@5468.09,4354.95 ccw(c5466.51,4372.99) 5480.38,4361.35 ; v3@5476.21,4348.13 cw(c5494.25,4349.71) 5480.38,4361.35 ; v1@5488.28,4868.28 cw(c5477.85,4857.85) 5492.6,4857.85 ; 5492.6,4846.28 cw(c5523.72,4846.28) v1@5501.72,4868.28 ; 5492.6,4855.94 cw(c5514.06,4855.94) v1@5498.89,4871.11 ; v1(5495,4875) 5492.6,4872.6 5492.6,4831.63 5492.6,4830 5492.6,4724.74 5492.6,4720 5492.6,4710 5492.6,4503.9 5492.6,4484.48 5492.6,4410.36 5492.6,4390.86 cw(c5450.87,4390.86) 5480.38,4361.35 ; v3@5509.41,4315.5 ccw(c5512.56,4333.33) 5522.94,4318.5 ; v3@5515.5,4306.81 cw(c5533.33,4303.66) 5522.94,4318.5 ; v3@5548.13,4276.21 ccw(c5549.71,4294.25) 5561.35,4280.38 ; v3@5554.95,4268.09 cw(c5572.99,4266.51) 5561.35,4280.38 ; 5910,4292.6 5590.86,4292.6 ccw(c5590.86,4250.87) 5561.35,4280.38 ; 5910,4410.62 5626.22,4410.62 ccw(c5626.22,4386.85) 5602.45,4386.85 cw(c5586.85,4386.85) 5586.85,4371.25 ccw(c5586.85,4347.48) 5563.08,4347.48 cw(c5547.48,4347.48) 5547.48,4331.88 ccw(c5547.48,4308.11) 5530.67,4324.92 5522.94,4318.5 ; v2@6961.19,1904.37 v2(6970.63,1904.37) ; v1@5234.86,5050.04 v1@5234.9,5050
  Bottom Layer w12: R207.2@3300.06,1630.75 cw(c3290.98,1621.67) 3303.82,1621.67 cw(c3316.66,1621.67) R207.2@3307.58,1630.75 ; R207.2@3303.82,1635 3303.82,1620 3313.82,1610 3395,1610 3406.93,1598.07 3406.93,1570 v1(3435,1541.93) ; v1@3429.5,1541.93 ccw(c3416.22,1541.93) 3425.61,1551.32 ccw(c3435,1560.71) v1@3435,1547.43 ; v1(5306.86,2858.37) 5306.86,2843.14 5315,2835 C193.1@5365.39,2835 C192.1@5365.39,2715 ; C192.1@5361.28,2719.11 ccw(c5351.36,2729.03) 5365.39,2729.03 ccw(c5379.42,2729.03) C192.1@5369.5,2719.11 ; C193.1@5361.28,2839.11 cw(c5351.36,2849.03) 5351.36,2835 cw(c5351.36,2820.97) 5361.28,2830.89 cw(c5351.36,2820.97) 5365.39,2820.97 cw(c5379.42,2820.97) C193.1@5369.5,2830.89
  other v1: 3435,1438.07 3457.5,1438.07 3480,1438.07 3555,1438 3577.5,1438 3600,1438 3622.5,1438 3645,1438 3667.5,1438 3457.5,1541.93 3480,1541.93 3348.7,1750.67 3470.75,1750.67 3348.7,1773.17 3470.75,1773.17 3348.7,1795.67 3470.75,1795.67 997.62,3003.81 997.31,3143.04
1V2SET: R207.1 R208.1 U42.5 | length 432.8
  Bottom Layer w12: R207.1@3346.18,1635 R208.1@3438.82,1635 3438.82,1598.01 3438.82,1581.18 3445,1575 3505,1575 3595,1575 3636.14,1533.86 U42.5@3636.14,1525 ; R207.1@3349.94,1631.24 cw(c3359.02,1622.16) 3359.02,1635 cw(c3359.02,1647.84) R207.1@3349.94,1638.76 ; R208.1@3435.06,1630.75 cw(c3425.98,1621.67) 3438.82,1621.67 cw(c3451.66,1621.67) R208.1@3442.58,1630.75 ; R208.1@3435.06,1631.24 ccw(c3425.98,1622.16) 3425.98,1635 ccw(c3425.98,1647.84) R208.1@3435.06,1638.76
1V8: C128.1 C129.1 EXTHDR1.77 EXTHDR1.79 PROTOTYPE1.4 R201.2 TP6.1 U39.2 | length 2633.3
  Top Layer w12: v1@902.98,3142.02 EXTHDR1.79@902.97,3071.85 v1@902.98,3142.88 ; v1@930.43,3139.15 cw(c920.66,3129.38) 934.47,3129.38 ; EXTHDR1.77@934.47,3071.85 v1@934.47,3142.88 ; 934.47,3130.14 cw(c947.21,3130.14) v1@938.2,3139.15 ; v1@898.93,3139.15 cw(c889.16,3129.38) 902.98,3129.38 ccw(c889.16,3129.38) v1@898.93,3139.15 ; 902.98,3130.14 cw(c915.72,3130.14) 906.71,3139.15 ccw(c915.72,3130.14) 902.98,3130.14
  MidLayer1 w20: TP6.1@56.12,3708.23 cw(c7.84,3708.23) 41.98,3674.09 cw(c76.12,3639.95) TP6.1@76.12,3688.23 ; TP6.1@76.12,3708.23 0,3632.11 0,3310 25,3285 452.89,3285 PROTOTYPE1.4@576.12,3408.23 ; PROTOTYPE1.4@555.12,3408.23 cw(c504.42,3408.23) 540.27,3372.39 cw(c576.12,3336.54) PROTOTYPE1.4@576.12,3387.23
  MidLayer2 w20: PROTOTYPE1.4@576.12,3387.23 cw(c576.12,3336.54) 611.97,3372.39 cw(c647.82,3408.23) PROTOTYPE1.4@597.12,3408.23 ; PROTOTYPE1.4@576.12,3408.23 639.36,3345 925,3345 955,3315 955,3210 934.31,3189.31 v1(934.31,3143.04)
  Bottom Layer w20: 2860.6,1684.26 cw(c2902.01,1642.85) v1@2902.01,1701.41 ; R201.2@2868.82,1625 2868.82,1692.48 C129.1@2940.28,1763.94 ; 2869.98,1693.64 cw(c2940.28,1623.34) C129.1@2940.28,1722.76 ; 2879.48,1703.14 ccw(c2822.62,1760) C129.1@2903.03,1760 ; 2883.51,1702.91 cw(c2893.78,1702.91) 2886.52,1710.18 ; C129.1@2894.74,1718.4 cw(c2902.01,1711.14) C129.1@2902.01,1721.41 ; v1@2903.51,1702.91 cw(c2962.07,1702.91) C129.1@2920.66,1744.32 ; C129.1@2904.12,1727.78 cw(c2940.28,1691.62) C129.1@2940.28,1742.76
  other v1: 2358,1438.01 2383,1438.01 2408,1438.01 2580,1450 2358,1464.01 2383,1464.01 2408,1464.01 2358,1490 2383,1490 2408,1490 2545,1490 2615,1490 2358,1516 2383,1516 2408,1516 2545,1516.67 2615,1516.67 2358,1542 2383,1542 2408,1542 2545,1543.33 2615,1543.33 2545,1570 2615,1570 2356.01,1584.87 2382,1584.87 2408,1584.87 2515,1605 2540.99,1605 2615,1605 2640.99,1605 2335,1617.01 2820,1629 2846,1629 2515,1630 2540.99,1630 2615,1630 2640.99,1630 2335,1643.01 2515,1655 2540.99,1655 2615,1655 2640.99,1655 2820,1655 2846,1655 2335,1669 2206.02,1670.99 2232.01,1670.99 2258.01,1670.99 2284,1671 2310,1671 2820,1681 2335,1695 2232.01,1695.99 2258.01,1695.99 2284,1696 2310,1696 2902.01,1702.91 2924.51,1702.91 2947.01,1702.91 3003,1711 3029,1711 3055,1711 3080.99,1711 3106.99,1711 3003,1736 3029,1736 3055,1736 3080.99,1736 3106.99,1736 2879.25,1740.67 2820,1760 2844,1760 3003,1761 3029,1761 3055,1761 3080.99,1761 3106.99,1761 2879.25,1763.17 2335,1768.01 2206.02,1770 2232.01,1770 2258.01,1770 2284,1770 2310,1770 2820,1785 2844,1785 2879.25,1785.67 2335,1794 2232.01,1795 2258.01,1795 2284,1795 2310,1795 2258.01,1820 2284,1820 2310,1820 2335,1820 2820,1871.99 2845,1871.99 2870,1871.99 2191.14,1885 2295,1885 3019.98,1887 3045.98,1887 3071.98,1887 3097.97,1887.01 2335,1894 2820,1897.99 2845,1897.99 2191.14,1907.5 2295,1907.5 2993.99,1912 3019.98,1912 3045.98,1912 3071.98,1912 3097.97,1912.01 2335,1920 2820,1923.98 2191.14,1930 2295,1930 2967.99,1937 2993.99,1937 3019.98,1937 3045.98,1937 3071.98,1937 3097.97,1937.01 2335,2010.02 2335,2036.01 2106,2040 2131.99,2040 2869.99,2053.96 2335,2062.01 2106,2065 2131.99,2065 2231.02,2088 2257.01,2088 2283.01,2088 2309,2088 2335,2088 2106,2090 2131.99,2090 2231.02,2114 2257.01,2114 2283.01,2114 2309,2114 2335,2114 2106,2115 2131.99,2115 2156.99,2115 2181.99,2115 2106,2140 2131.99,2140 2156.99,2141 2181.99,2141 2106,2165 2131.99,2165 2106,2190 2131.99,2190 2362.01,2191.99 2388.01,2191.99 2414,2191.99 2440,2191.99 2362.01,2216.99 2388.01,2216.99 2414,2216.99 2440,2216.99 2336.01,2241.99 2362.01,2241.99 2388.01,2241.99 2414,2241.99 2440,2241.99 902.82,3143.04
1V8SET: R201.1 R202.1 U39.1 | length 450.7
  Bottom Layer w12: U39.1@2680,1525 2715,1560 2880,1560 2911.18,1591.18 R201.1@2911.18,1625 ; R201.1@2906.09,1625 R201.1@2911.18,1625 ; R201.1@2907.42,1620.75 cw(c2898.34,1611.67) 2911.18,1611.67 cw(c2924.02,1611.67) R201.1@2914.94,1620.75 ; R201.1@2914.94,1621.24 cw(c2924.02,1612.16) 2924.02,1625 cw(c2924.02,1637.84) R201.1@2914.94,1628.76 ; R202.1@3000.06,1621.24 ccw(c2990.98,1612.16) 2990.98,1625 ccw(c2990.98,1637.84) R202.1@3000.06,1628.76 ; R202.1@3003.82,1625 R201.1@2911.18,1625
2V5: C132.1 C133.1 C138.1 C139.1 EXTHDR1.81 EXTHDR1.83 PROTOTYPE1.6 R203.2 TP5.1 U40.2 U42.1 U42.2 | length 1570
  Top Layer w12: v1@835.94,3139.15 cw(c826.17,3129.38) 839.98,3129.38 ; EXTHDR1.83@839.98,3071.85 v1@839.98,3142.88 ; 839.98,3130.14 cw(c852.73,3130.14) v1@843.72,3139.15 ; v1@867.43,3139.15 cw(c857.66,3129.38) 871.48,3129.38 ; EXTHDR1.81@871.48,3071.85 v1@871.48,3142.88 ; 871.48,3130.14 cw(c884.22,3130.14) v1@875.21,3139.15
  MidLayer2 w20: TP5.1@76.12,3788.23 cw(c76.12,3739.95) 110.26,3774.09 cw(c144.41,3808.23) TP5.1@96.12,3808.23 ; TP5.1@76.12,3808.23 124.36,3760 710,3760 725,3745 725,3459.36 PROTOTYPE1.6@776.12,3408.23 ; PROTOTYPE1.6@755.12,3408.23 ccw(c704.42,3408.23) 740.27,3444.08 ccw(c776.12,3479.93) PROTOTYPE1.6@776.12,3429.23
  Bottom Layer w12: R203.2@1780.06,1629.25 ccw(c1770.98,1638.33) 1783.82,1638.33 ccw(c1796.66,1638.33) R203.2@1787.58,1629.25 ; R203.2@1783.82,1625 1783.82,1654.72 v1@1832.01,1702.91 ; 1809.82,1680.72 ccw(c1787.62,1702.91) v1@1819.01,1702.91 ; 1812.01,1682.92 cw(c1847.01,1647.92) v1@1847.01,1697.41 ; v1@1832.5,1703.4 cw(c1847.01,1688.89) v1@1847.01,1709.41
  other v1: 1273,1438.01 1298,1438.01 1323,1438.01 4054.02,1438.07 4076.52,1438.07 4099.02,1438.07 1495,1450 1273,1464.01 1298,1464.01 1323,1464.01 1273,1490 1298,1490 1323,1490 1460,1490 1530,1490 1273,1516 1298,1516 1323,1516 1460,1516.67 1530,1516.67 1273,1542 1298,1542 1323,1542 4054.02,1541.93 4076.52,1541.93 4099.02,1541.93 1460,1543.33 1530,1543.33 1460,1570 1530,1570 1271,1585 1297,1585 1322.99,1585 1637.01,1585 1663.01,1585 1689,1585 1715,1585 1430,1605 1456,1605 1530,1605 1556,1605 1735,1607.01 1760.01,1608.05 1255,1609 1430,1630 1456,1630 1530,1630 1556,1630 1735,1633.01 1760.01,1634.04 1255,1635 1430,1655 1456,1655 1530,1655 1556,1655 1735,1659 1760.01,1660.04 1255,1661 1923,1668.01 1948,1668.01 1973,1668.01 1998,1668.01 2023,1668.01 1735,1685 1760.01,1686.04 1255,1686.99 1923,1694.01 1948,1694.01 1973,1694.01 1998,1694.01 2023,1694.01 1106.02,1700 1132.01,1700 1158.01,1700 1184,1700 1210,1700 1802.01,1702.91 1824.51,1702.91 1847.01,1702.91 4107.01,1702.91 4129.51,1702.91 4152.01,1702.91 1735,1711 1760.01,1712.03 1255,1712.99 1923,1720 1948,1720 1973,1720 1998,1720 2023,1720 1106.02,1725 1132.01,1725 1158.01,1725 1184,1725 1210,1725 1735,1736.99 1760.01,1738.03 1255,1738.98 1923,1746 1948,1746 1973,1746 1998,1746 2023,1746 1106.02,1750 1132.01,1750 1158.01,1750 1184,1750 1210,1750 1735,1762.99 1760,1764.02 1255,1764.98 1923,1772 1948,1772 1973,1772 1998,1772 1106.02,1775 1132.01,1775 1158.01,1775 1184,1775 1210,1775 1735,1788.98 1760,1790.02 1255,1790.98 1735,1814.98 1760,1816.02 1802.01,1824.96 1824.51,1824.96 1847.01,1824.96 4107.01,1824.96 4129.51,1824.96 4152.01,1824.96 1735,1840.98 1760,1842.01 1250.77,1856.04 1250.77,1882.03 1106.14,1885 1210,1885 1106.14,1907.5 1210,1907.5 1250.77,1908.03 1734.99,1926.97 1760,1928.01 1106.14,1930 1210,1930 1250.77,1934.03 1734.99,1952.97 1760,1954 1734.99,1978.96 1760,1980 1250,2010 1735,2025 1250,2036 1735,2074 1735,2100 1735,2126 1331,2145 1356.99,2145 1426,2145 1451.99,2145 1477.99,2145 1503.98,2145 1529.98,2145 1555.98,2145 1581.97,2145.01 1607.97,2145.01 1633.96,2145.01 1659.96,2145.01 1685.96,2145.01 1711.95,2145.01 1829,2172 1855,2172 1880.99,2172 1906.99,2172 1803,2197 1829,2197 1855,2197 1880.99,2197 1906.99,2197 1803,2222 1829,2222 1855,2222 1880.99,2222 1906.99,2222 1803,2247 1829,2247 1855,2247 1880.99,2247 1906.99,2247 839.83,3143.04 871.32,3143.04
2V5SET: R203.1 R204.1 U40.1 | length 445.6
  Bottom Layer w12: U40.1@1595,1520 1630,1555 1795,1555 1826.18,1586.18 R203.1@1826.18,1620 ; R203.1@1822.42,1620.75 cw(c1813.34,1611.67) 1826.18,1611.67 cw(c1839.02,1611.67) R203.1@1829.94,1620.75 ; R203.1@1826.18,1625 R204.1@1918.82,1625 ; R203.1@1829.94,1621.24 cw(c1839.02,1612.16) 1839.02,1625 cw(c1839.02,1637.84) R203.1@1829.94,1628.76 ; R204.1@1915.06,1621.24 ccw(c1905.98,1612.16) 1905.98,1625 ccw(c1905.98,1637.84) R204.1@1915.06,1628.76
